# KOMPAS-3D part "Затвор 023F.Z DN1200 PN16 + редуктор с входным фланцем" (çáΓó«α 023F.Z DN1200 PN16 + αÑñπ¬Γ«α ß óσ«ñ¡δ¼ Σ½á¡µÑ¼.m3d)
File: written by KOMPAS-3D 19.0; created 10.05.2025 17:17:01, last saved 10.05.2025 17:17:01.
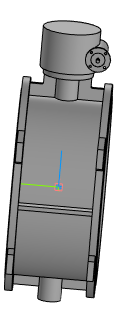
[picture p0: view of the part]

Document properties: Полное имя файла: Затвор 023F.Z DN1200 PN16 + редуктор с входным фланцем.a3d

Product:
- Part/product: Затвор 023F.Z DN1200 PN16 + редуктор с входным фланцем
    Масса: 2204.98

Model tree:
1. Операция без истории:1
